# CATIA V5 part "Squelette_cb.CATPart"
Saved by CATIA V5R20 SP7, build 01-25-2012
Part number: Squelette_cpeb
Publications: "Plan.2", "Droite.5", "Droite.6"
Bounding box of the stored display mesh (mm): x 0 to 20, y 3.472 to 37.674, z 98.928 to 192.897
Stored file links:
  G:\bon\Nouveau dossier\Squelette_cb.CATPart
  C:\Documents and Settings\cgirerd\Bureau\Copie de Copie de Nouveau dossier\765.CATProduct
  G:\bon\Nouveau dossier\mecanism.skl.CATProduct
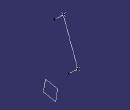
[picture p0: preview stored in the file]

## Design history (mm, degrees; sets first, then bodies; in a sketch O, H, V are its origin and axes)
Set1
  Point1 "C": linked copy from another document
  Point2 "B": linked copy from another document
  Plane1: linked copy from another document
Set2
  Line1: type PtPt, FirstPoint Point1, SecondPoint Point2
  Line2: type Normal, RefPoint Point1, RefSkin Plane1, Start 0, End 20
  Line3: type Normal, RefPoint Point2, RefSkin Plane1, Start 0, End 20
Body1 (main body)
